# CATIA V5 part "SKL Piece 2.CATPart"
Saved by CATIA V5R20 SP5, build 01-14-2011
Part number: SKL Piece 2
Publications: "Plan.1", "Plan.2", "Droite.1", "Droite.2"
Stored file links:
  G:\IAO Final\SKL Piece 2.CATPart
  G:\IAO Final\Assemblage Final.CATProduct
  G:\IAO Final\SKL Tige.CATPart
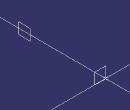
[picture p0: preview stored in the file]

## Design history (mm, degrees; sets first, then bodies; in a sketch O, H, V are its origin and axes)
Set1
  Point1: linked copy from another document
Body1 (main body)
  Plane1: type Offset, RefPlane yz-plane, Offset 0
  Plane2: type Offset, RefPlane zx-plane, Offset 500
  Line1: type Normal, RefPoint Point1, RefSkin Plane1, Start 0, End 20
  Line2: type Normal, RefPoint Point1, RefSkin Plane2, Start 0, End 20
